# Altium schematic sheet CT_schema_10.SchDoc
size 297 x 239 mm
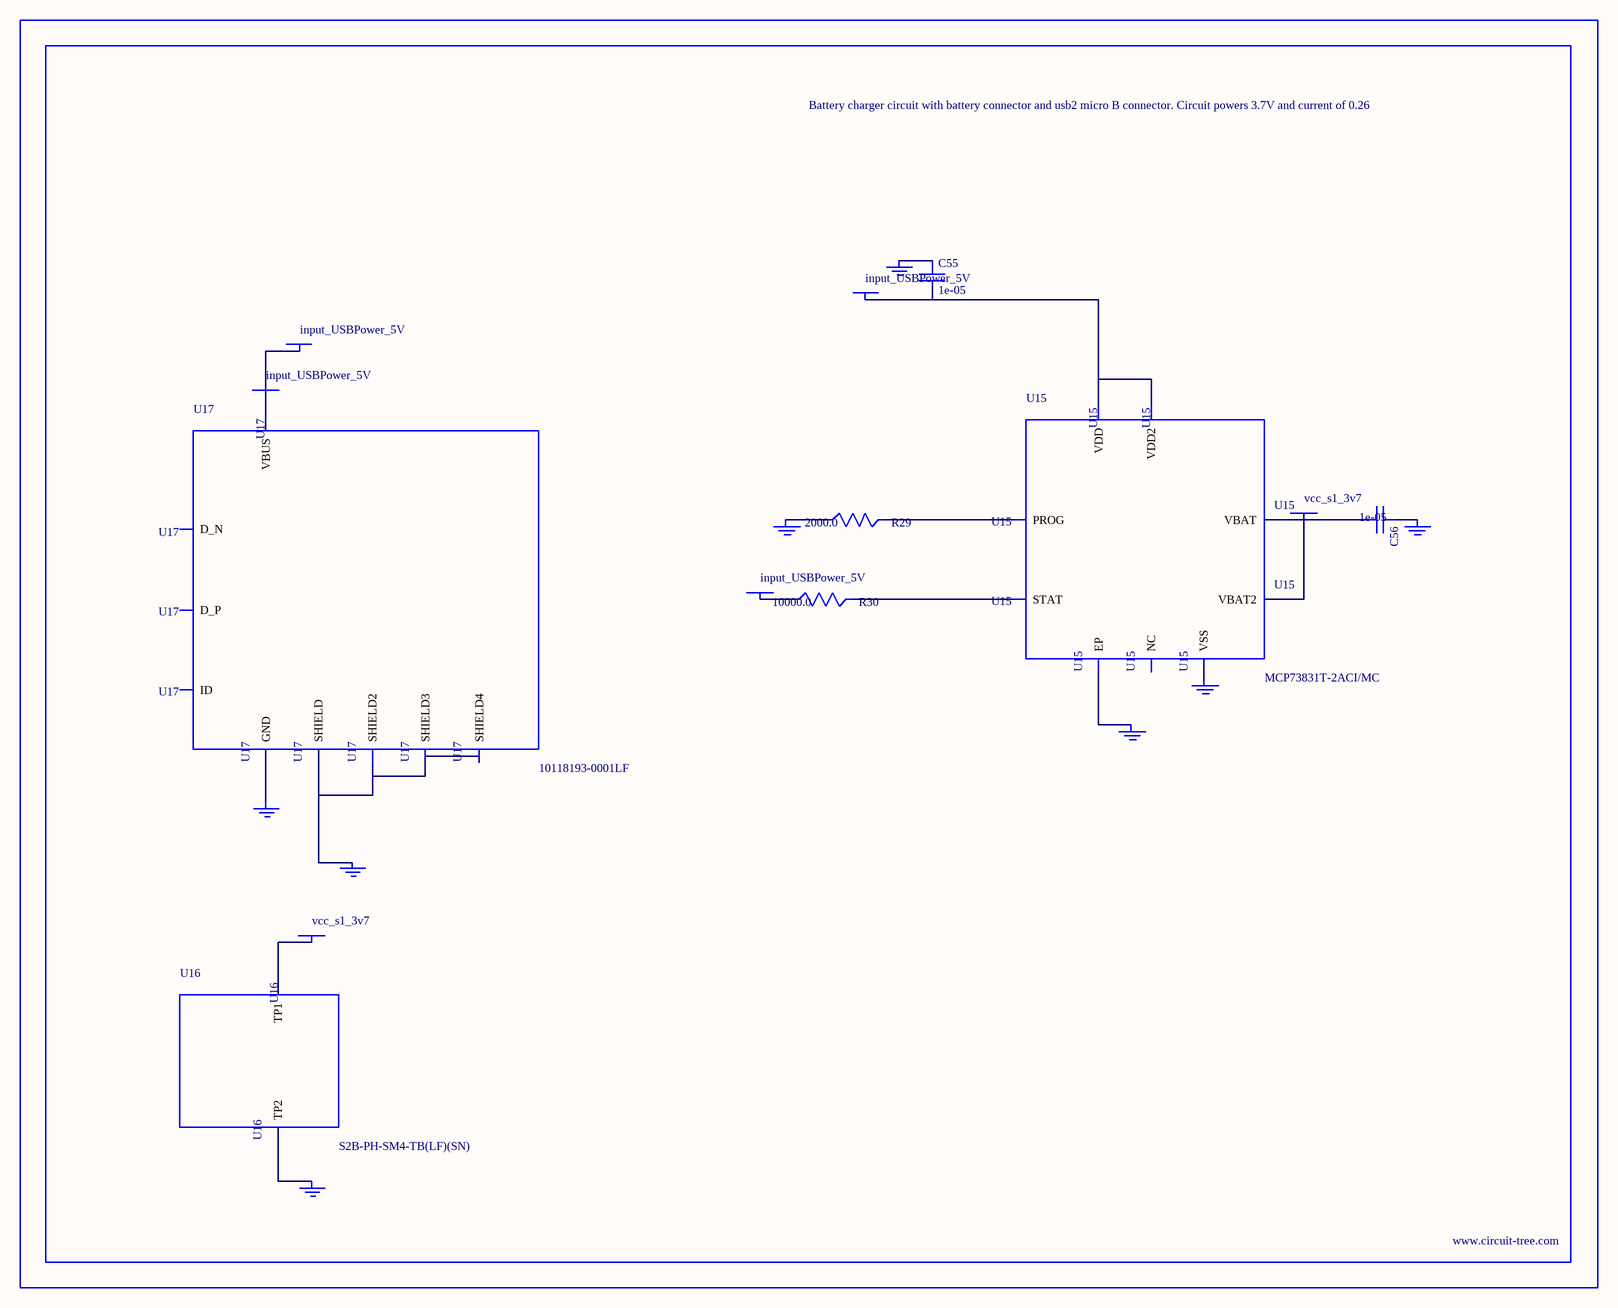
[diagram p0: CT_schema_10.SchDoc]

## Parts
BORDER9  (no value)
C55  1e-05  [C1206]
C56  1e-05  [C1206]
GND_INSTANCE_9_0  (no value)
GND_INSTANCE_9_1  (no value)
GND_INSTANCE_9_2  (no value)
GND_INSTANCE_9_3  (no value)
GND_INSTANCE_9_4  (no value)
GND_INSTANCE_9_5  (no value)
GND_INSTANCE_9_6  (no value)
GND_INSTANCE_9_7  (no value)
POWER_INSTANCE_9_0  input_USBPower_5V
POWER_INSTANCE_9_1  input_USBPower_5V
POWER_INSTANCE_9_2  vcc_s1_3v7
POWER_INSTANCE_9_3  vcc_s1_3v7
POWER_INSTANCE_9_4  input_USBPower_5V
POWER_INSTANCE_9_5  input_USBPower_5V
R29  2000.0  [R0603]
R30  10000.0  [R0603]
U15  MCP73831T-2ACI/MC  [DFN8_2X3MC]
U16  S2B-PH-SM4-TB(LF)(SN)  [JST-2-SMD]
U17  10118193-0001LF  [FCI_10118193-0001LF]

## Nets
NetC55_1: C55.1 GND_INSTANCE_9_0.0(GND)
NetC55_2: C55.2 POWER_INSTANCE_9_0.0(PWR) U15.1(VDD) U15.2(VDD2)
NetC56_1: C56.1 GND_INSTANCE_9_1.0(GND)
NetC56_2: C56.2 POWER_INSTANCE_9_2.0(PWR) U15.3(VBAT) U15.4(VBAT2)
NetGND_INSTANCE_9_2_0: GND_INSTANCE_9_2.0(GND) R29.1
NetGND_INSTANCE_9_3_0: GND_INSTANCE_9_3.0(GND) U15.9(EP)
NetGND_INSTANCE_9_4_0: GND_INSTANCE_9_4.0(GND) U15.6(VSS)
NetGND_INSTANCE_9_5_0: GND_INSTANCE_9_5.0(GND) U16.2(TP2)
NetGND_INSTANCE_9_6_0: GND_INSTANCE_9_6.0(GND) U17.6(SHIELD) U17.7(SHIELD2) U17.8(SHIELD3) U17.9(SHIELD4)
NetGND_INSTANCE_9_7_0: GND_INSTANCE_9_7.0(GND) U17.5(GND)
NetPOWER_INSTANCE_9_1_0: POWER_INSTANCE_9_1.0(PWR) R30.1
NetPOWER_INSTANCE_9_3_0: POWER_INSTANCE_9_3.0(PWR) U16.1(TP1)
NetPOWER_INSTANCE_9_4_0: POWER_INSTANCE_9_4.0(PWR) POWER_INSTANCE_9_5.0(PWR) U17.1(VBUS)
NetR29_2: R29.2 U15.8(PROG)
NetR30_2: R30.2 U15.5(STAT)

Not connected (* = marked no-connect by the designer): U15 7(NC); U17 2(D_N) 3(D_P) 4(ID)

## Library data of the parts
BORDER9 = BORDER_PAGE9
C55 C56 = C1206C106K3RACTU
GND_INSTANCE_9_0-GND_INSTANCE_9_7 = GND
POWER_INSTANCE_9_0-POWER_INSTANCE_9_5 = PWR
R29 = RC0603JR-072KL
R30 = RC0603JR-0710KL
